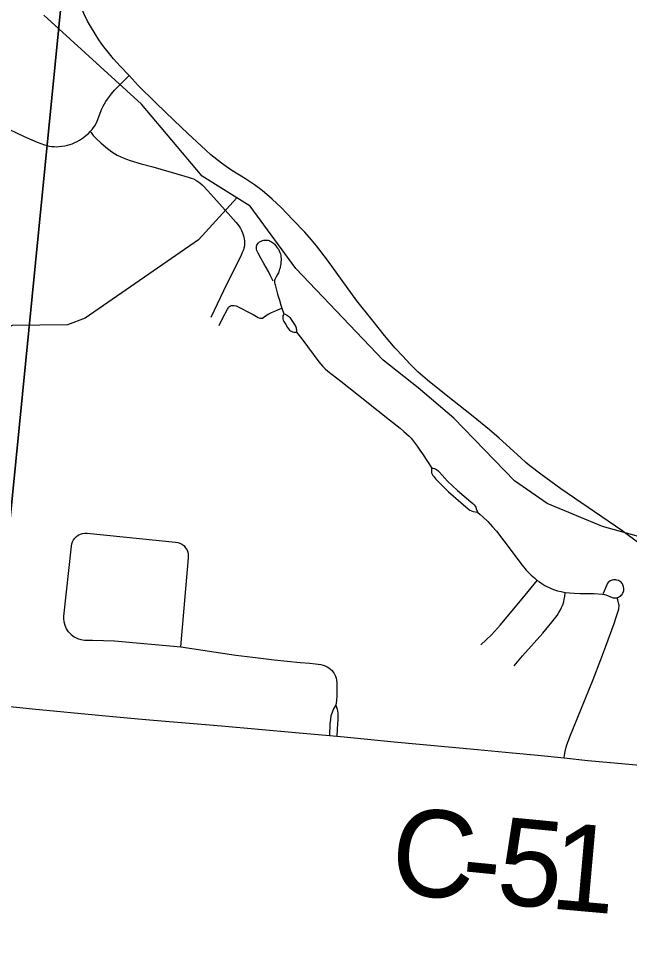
# Model space of a CAD drawing. Extents: x 0 to 34, y 0 to 22.
# Drawn here: x 25.829 to 26.229, y 14.002 to 14.618 of the extents above; entities that cross this region are included whole.
import ezdxf

# ---------------------------------------------------------------- set-up
doc = ezdxf.new("R2010")
doc.units = 0
for name, color, linetype in [('GM_X_City_Street', 7, 'Continuous'), ('GM_X_County_Road', 7, 'Continuous'), ('GM_X_County_Road_Text', 7, 'Continuous'), ('GM_X_Minor_River', 7, 'Continuous'), ('GM_X_Section', 7, 'Continuous')]:
    doc.layers.add(name, color=color, linetype=linetype)

msp = doc.modelspace()

# ---------------------------------------------------------------- linework, layer by layer
at = {"layer": 'GM_X_City_Street'}
msp.add_line((26.00175, 14.4284), (26.00308, 14.42476), dxfattribs=at)
for points in [[(25.87622, 14.54403), (25.87748, 14.54535), (25.87842, 14.54667), (25.87925, 14.54786), (25.88003, 14.54926), (25.88077, 14.55082), (25.88392, 14.55901), (25.88463, 14.5606), (25.88554, 14.56226), (25.88648, 14.5638), (25.8875, 14.56533), (25.88874, 14.56705), (25.89008, 14.56873), (25.89211, 14.57108), (25.8947, 14.5738), (25.89799, 14.57704), (25.90163, 14.58064)], [(25.81826, 14.54775), (25.83287, 14.54078), (25.84146, 14.53708), (25.84621, 14.53534), (25.84781, 14.53487), (25.84932, 14.53456), (25.85097, 14.53429), (25.85254, 14.53418), (25.8541, 14.53413), (25.85575, 14.53421), (25.85763, 14.53442), (25.85956, 14.53472), (25.86125, 14.53508), (25.86289, 14.53557), (25.86449, 14.5361), (25.86622, 14.53684), (25.86762, 14.53754), (25.86911, 14.53836), (25.87045, 14.53919), (25.87177, 14.54017), (25.87341, 14.54145), (25.87501, 14.54276), (25.87622, 14.54403)], [(25.87622, 14.54403), (25.87676, 14.54336), (25.87821, 14.54155), (25.8805, 14.53917), (25.88326, 14.53658), (25.88646, 14.53382), (25.89035, 14.53088), (25.8921, 14.52968), (25.89396, 14.52862), (25.8958, 14.52762), (25.89776, 14.52675), (25.89995, 14.52589), (25.90233, 14.52507), (25.90953, 14.52297), (25.91722, 14.52088), (25.93811, 14.51495), (25.94029, 14.51428), (25.94234, 14.51363), (25.94395, 14.51301), (25.94539, 14.51227), (25.94662, 14.5114), (25.94795, 14.51042), (25.94946, 14.50919), (25.95081, 14.50787), (25.95709, 14.50093), (25.96823, 14.48845), (25.9716, 14.48471), (25.97284, 14.48313), (25.97387, 14.48164), (25.97453, 14.48058), (25.97518, 14.47941), (25.97588, 14.47787), (25.9764, 14.4764), (25.97675, 14.4752), (25.97703, 14.47387), (25.9772, 14.47252), (25.97729, 14.47124), (25.97728, 14.47026), (25.97715, 14.46924), (25.97687, 14.46784), (25.97652, 14.4667), (25.9758, 14.46484), (25.97505, 14.46314), (25.96343, 14.4398), (25.95511, 14.42245)], [(25.99597, 14.4462), (25.99433, 14.44958), (25.99285, 14.45242), (25.98987, 14.45776), (25.98797, 14.46122), (25.98616, 14.46442), (25.98576, 14.46529), (25.98539, 14.46619), (25.98519, 14.46705), (25.98506, 14.46804), (25.98512, 14.46902), (25.98539, 14.46977), (25.98572, 14.47038), (25.98613, 14.47092), (25.98711, 14.47178), (25.98778, 14.47218), (25.98859, 14.4726), (25.98929, 14.47285), (25.98999, 14.47301), (25.99087, 14.47308), (25.9918, 14.47305), (25.99266, 14.47288), (25.99336, 14.47268), (25.99406, 14.47239), (25.99484, 14.47198), (25.99554, 14.47149), (25.99623, 14.47092), (25.99684, 14.47032), (25.99784, 14.46919), (25.9987, 14.46804), (25.9994, 14.46705), (25.99994, 14.46604), (26.00043, 14.46496), (26.00077, 14.46406), (26.00101, 14.4631), (26.00112, 14.46217), (26.00121, 14.46107), (26.0012, 14.46), (26.00109, 14.45856), (26.00097, 14.45745), (26.0008, 14.45634), (26.00063, 14.45541), (26.00032, 14.45427), (26.00004, 14.45334), (25.99969, 14.45235), (25.9994, 14.4516), (25.9989, 14.45061), (25.99796, 14.44892), (25.99748, 14.44806), (25.99718, 14.44727), (25.99697, 14.44651), (25.99689, 14.44588), (25.99692, 14.44518), (25.99706, 14.44436), (25.99723, 14.44372), (25.99893, 14.43767), (26.00006, 14.43363), (26.00104, 14.43043), (26.00175, 14.4284)], [(25.96072, 14.41721), (25.96292, 14.42162), (25.96611, 14.42788), (25.96644, 14.42854), (25.96685, 14.42912), (25.96738, 14.42961), (25.96804, 14.42998), (25.9687, 14.43018), (25.96989, 14.43031), (25.97055, 14.43027), (25.97174, 14.43002), (25.98284, 14.42436), (25.9861, 14.42248), (25.98727, 14.422), (25.9879, 14.42192), (25.98905, 14.42204), (25.99102, 14.42345), (25.99308, 14.4248), (25.99484, 14.4257), (25.99701, 14.42662), (25.99916, 14.42743), (26.00175, 14.4284)], [(26.00308, 14.42476), (26.00275, 14.4241), (26.00245, 14.42336), (26.00225, 14.4225), (26.00234, 14.42155), (26.00262, 14.42069), (26.003, 14.41986), (26.00423, 14.41781), (26.00546, 14.41588), (26.00677, 14.41415), (26.00726, 14.41371), (26.00782, 14.41338), (26.00871, 14.41305), (26.00959, 14.41284), (26.01035, 14.41272), (26.01119, 14.41268)], [(26.00308, 14.42476), (26.00394, 14.42447), (26.00468, 14.42414), (26.00533, 14.42377), (26.00599, 14.42328), (26.00682, 14.42229), (26.00817, 14.4204), (26.00994, 14.41773), (26.01064, 14.41662), (26.01107, 14.41564), (26.01117, 14.4149), (26.01123, 14.4142), (26.01119, 14.41268)], [(26.01119, 14.41268), (26.01469, 14.40835), (26.01848, 14.40338), (26.02595, 14.39332), (26.02714, 14.39183), (26.02856, 14.39022), (26.03004, 14.38881), (26.03182, 14.38725), (26.04022, 14.38064), (26.05187, 14.37158), (26.06475, 14.36132), (26.07225, 14.35541), (26.07924, 14.34987), (26.08152, 14.34787), (26.08334, 14.34632), (26.08498, 14.34475), (26.08634, 14.34332), (26.08774, 14.34167), (26.08909, 14.33995), (26.09041, 14.3381), (26.09212, 14.33566), (26.09386, 14.33318), (26.09713, 14.32816), (26.09993, 14.32388)], [(26.09993, 14.32388), (26.09977, 14.32314), (26.09964, 14.3224), (26.09964, 14.32162), (26.09974, 14.32079), (26.10005, 14.31989), (26.10063, 14.31903), (26.10126, 14.31822), (26.10256, 14.31668), (26.10552, 14.31348), (26.11084, 14.3084), (26.11887, 14.30141), (26.12365, 14.29712), (26.12472, 14.29634), (26.12582, 14.29581), (26.12698, 14.29548), (26.12975, 14.29506)], [(26.09993, 14.32388), (26.10079, 14.32376), (26.10171, 14.32354), (26.10258, 14.32322), (26.10322, 14.32277), (26.10393, 14.32215), (26.10471, 14.32129), (26.10667, 14.31915), (26.11025, 14.31521), (26.11345, 14.31216), (26.11682, 14.30906), (26.12537, 14.30177), (26.12665, 14.3007), (26.12759, 14.29971), (26.12819, 14.29895), (26.12862, 14.29815), (26.12901, 14.29719), (26.12975, 14.29506)], [(26.12975, 14.29506), (26.13158, 14.29355), (26.13354, 14.29182), (26.13658, 14.28877), (26.13967, 14.28538), (26.14217, 14.28248), (26.14711, 14.27617), (26.15903, 14.26037), (26.16172, 14.25703), (26.16336, 14.25529), (26.16505, 14.25373), (26.16706, 14.25192), (26.16899, 14.25036)], [(25.862, 14.2167), (25.86069, 14.21868), (25.85973, 14.22084), (25.85914, 14.22314), (25.85894, 14.2255), (25.85902, 14.227), (25.86388, 14.27276), (25.86414, 14.27419), (25.86462, 14.27556), (25.8653, 14.27684), (25.86617, 14.278), (25.8672, 14.27901), (25.86843, 14.27989), (25.86979, 14.28056)], [(25.86979, 14.28056), (25.87123, 14.28101), (25.87273, 14.28122), (25.87424, 14.28119), (25.93214, 14.27541), (25.93358, 14.27515), (25.93497, 14.27467), (25.93626, 14.27399), (25.93743, 14.27311), (25.93846, 14.27207)], [(25.9355, 14.20686), (25.94063, 14.2652), (25.94067, 14.26599), (25.94053, 14.26763), (25.9401, 14.26922), (25.9394, 14.27072), (25.93846, 14.27207)], [(26.13209, 14.20824), (26.13906, 14.21477), (26.14498, 14.22125), (26.15022, 14.2276), (26.15906, 14.23834), (26.16899, 14.25036)], [(26.16899, 14.25036), (26.17035, 14.24937), (26.17191, 14.24833), (26.17387, 14.24708), (26.1752, 14.24629), (26.17666, 14.24559), (26.17838, 14.24487), (26.18023, 14.24426), (26.18227, 14.24358), (26.18467, 14.24297), (26.18724, 14.24247)], [(26.22123, 14.23895), (26.2222, 14.23936), (26.2228, 14.23971), (26.2234, 14.24011), (26.22395, 14.2406), (26.22447, 14.24113), (26.22486, 14.24175), (26.22517, 14.24238), (26.2254, 14.24303), (26.22556, 14.24372), (26.22566, 14.2445), (26.22563, 14.24526), (26.22546, 14.24614), (26.22524, 14.24678), (26.22497, 14.24744), (26.22468, 14.24803), (26.22431, 14.2486), (26.22384, 14.24915), (26.22332, 14.24957), (26.22279, 14.2499), (26.22221, 14.25019), (26.22114, 14.25052), (26.22043, 14.25068), (26.21962, 14.25078), (26.2189, 14.25073), (26.21805, 14.25058), (26.21724, 14.25035), (26.21658, 14.24997), (26.21553, 14.24912), (26.21511, 14.24864), (26.21473, 14.24801), (26.21441, 14.24743), (26.21211, 14.24166)], [(26.1538, 14.19433), (26.15932, 14.20105), (26.17254, 14.21589), (26.17859, 14.22296), (26.1819, 14.22745), (26.18309, 14.22928), (26.18418, 14.23115), (26.1849, 14.23256), (26.18553, 14.23395), (26.18593, 14.23503), (26.1863, 14.2363), (26.18667, 14.23811), (26.18691, 14.2398), (26.18724, 14.24247)], [(26.18724, 14.24247), (26.19016, 14.24223), (26.19317, 14.24199), (26.19696, 14.24182), (26.20625, 14.24167), (26.21166, 14.24138), (26.21207, 14.24133), (26.2123, 14.24131), (26.21296, 14.24119), (26.21387, 14.2409), (26.21793, 14.23921), (26.2187, 14.23899), (26.21932, 14.23888), (26.21998, 14.23886), (26.22123, 14.23895)], [(26.18651, 14.13417), (26.18676, 14.13593), (26.18726, 14.13828), (26.18817, 14.14205), (26.19029, 14.14803), (26.20549, 14.18545), (26.21048, 14.19867), (26.21378, 14.20722), (26.21927, 14.22221), (26.22067, 14.22619), (26.22157, 14.22895), (26.22229, 14.23157), (26.22244, 14.23248), (26.22248, 14.23326), (26.22248, 14.23404), (26.22235, 14.23486), (26.2222, 14.23565), (26.22195, 14.23651), (26.22166, 14.23762), (26.22123, 14.23895)], [(25.862, 14.2167), (25.86367, 14.21493), (25.86561, 14.21346), (25.86778, 14.21235), (25.8701, 14.21163), (25.87252, 14.21131), (25.87765, 14.21115), (25.89222, 14.21073), (25.9355, 14.20686)], [(25.9355, 14.20686), (25.97163, 14.20143), (25.98262, 14.20002), (25.99676, 14.19846), (26.01379, 14.1967), (26.02, 14.19613), (26.02379, 14.19579), (26.02558, 14.19554), (26.02718, 14.19526), (26.02866, 14.19488), (26.03006, 14.19439), (26.03133, 14.19386), (26.03252, 14.19312), (26.03363, 14.19226), (26.03454, 14.19127), (26.03528, 14.19037), (26.03593, 14.18942), (26.03647, 14.18851), (26.03684, 14.18757), (26.03716, 14.18646), (26.03751, 14.18496), (26.0377, 14.1835), (26.03779, 14.18199), (26.03778, 14.17869), (26.03766, 14.17478), (26.03745, 14.17179), (26.03713, 14.1687)], [(26.03713, 14.1687), (26.03626, 14.16743), (26.03556, 14.1662), (26.03503, 14.16513), (26.03454, 14.16385), (26.03413, 14.16278), (26.03384, 14.16167), (26.03347, 14.15941), (26.03306, 14.15641), (26.03291, 14.14876)], [(26.03713, 14.1687), (26.03754, 14.16734), (26.03787, 14.16607), (26.03815, 14.16475), (26.03832, 14.16348), (26.0384, 14.16241), (26.0384, 14.16126), (26.03832, 14.15933), (26.0382, 14.15645), (26.03799, 14.15292), (26.03772, 14.14835)]]:
    msp.add_lwpolyline(points, dxfattribs=at)
at = {"layer": 'GM_X_County_Road'}
for points in [[(25.87453, 14.61636), (25.8721, 14.62136), (25.87108, 14.62355), (25.87017, 14.62561), (25.8697, 14.62676), (25.8688, 14.62904), (25.8682, 14.63064), (25.86634, 14.63651), (25.86541, 14.63972), (25.86393, 14.64482), (25.86299, 14.64839), (25.86216, 14.65181), (25.8617, 14.65383), (25.86061, 14.6601), (25.85984, 14.66673), (25.85945, 14.67503), (25.85955, 14.6783)], [(25.90163, 14.58064), (25.8958, 14.58678), (25.89155, 14.59158), (25.88704, 14.59713), (25.88509, 14.59954), (25.88336, 14.60185), (25.88196, 14.60398), (25.87939, 14.60809), (25.87649, 14.61292), (25.87453, 14.61636)], [(25.95195, 14.53194), (25.94009, 14.54271), (25.93129, 14.55129), (25.91914, 14.56292), (25.90768, 14.57426), (25.90163, 14.58064)], [(25.97786, 14.51306), (25.96902, 14.51855), (25.96674, 14.52006), (25.96212, 14.52336), (25.9553, 14.5289), (25.95195, 14.53194)], [(26.22427, 14.28304), (26.18449, 14.3102), (26.17119, 14.3198), (26.164, 14.32533), (26.16153, 14.32738), (26.15811, 14.33046), (26.14403, 14.34343), (26.13777, 14.3489), (26.12701, 14.35755), (26.11347, 14.36838), (26.09951, 14.37937), (26.09712, 14.38134), (26.09106, 14.38666), (26.0855, 14.39208), (26.08084, 14.397), (26.07591, 14.40238), (26.06892, 14.41066), (26.06059, 14.42111), (26.0509, 14.43331), (26.03149, 14.45981), (26.02432, 14.46928), (26.02104, 14.47323), (26.01664, 14.47815), (26.00895, 14.48637), (26.00116, 14.49436), (25.99543, 14.49975), (25.99367, 14.50133), (25.98874, 14.50548), (25.98379, 14.50914), (25.97786, 14.51306)], [(26.23889, 14.27216), (26.23457, 14.27527), (26.22427, 14.28304)], [(25.70784, 14.17932), (25.71166, 14.17894), (25.71413, 14.1787), (25.74385, 14.17578), (25.76149, 14.17407), (25.77959, 14.17237), (25.83833, 14.16621), (25.88413, 14.16191), (25.90271, 14.16022), (25.9151, 14.1592), (25.93589, 14.15745), (25.96221, 14.15514)], [(25.96221, 14.15514), (26.01067, 14.15074), (26.03291, 14.14876)], [(26.03291, 14.14876), (26.03772, 14.14835), (26.04248, 14.14794)], [(26.04248, 14.14794), (26.07522, 14.1447), (26.12974, 14.13958), (26.15273, 14.13753), (26.16927, 14.13598), (26.18651, 14.13417)], [(26.18651, 14.13417), (26.20201, 14.1325), (26.21687, 14.13111), (26.26021, 14.12719), (26.30228, 14.12314), (26.31835, 14.12133), (26.33074, 14.12006), (26.36939, 14.11675), (26.39565, 14.11435)]]:
    msp.add_lwpolyline(points, dxfattribs=at)
at = {"layer": 'GM_X_Minor_River'}
for points in [[(26.24705, 14.27571), (26.21159, 14.28554), (26.17547, 14.3007), (26.15415, 14.31555), (26.11438, 14.3566), (26.09088, 14.37643), (26.0681, 14.39435), (26.01088, 14.45434), (25.98097, 14.49518), (25.9495, 14.5148), (25.90985, 14.56191), (25.84577, 14.62015)], [(25.97221, 14.50064), (25.94715, 14.4731), (25.87291, 14.42184), (25.86144, 14.41752), (25.82502, 14.41712), (25.79897, 14.40436), (25.77309, 14.38135), (25.75202, 14.37115), (25.71621, 14.36353), (25.68216, 14.36801), (25.66081, 14.36275), (25.63319, 14.32839), (25.62283, 14.32253), (25.61427, 14.31169), (25.60942, 14.27763), (25.59796, 14.27369), (25.57728, 14.28321), (25.55662, 14.27452), (25.50382, 14.27066), (25.49275, 14.26709), (25.45836, 14.25488), (25.39712, 14.24663)]]:
    msp.add_lwpolyline(points, dxfattribs=at)
at = {"layer": 'GM_X_Section'}
for points in [[(25.86182, 14.67437), (25.76091, 13.65822), (24.71962, 13.7501), (24.8195, 14.77309)], [(26.85675, 14.57345), (26.75942, 13.56709), (25.76091, 13.65822), (25.86182, 14.67437)]]:
    msp.add_lwpolyline(points, close=True, dxfattribs=at)

# ---------------------------------------------------------------- texts
at = {"layer": 'GM_X_County_Road_Text'}
for s, rotation, p in [('C', 354.39019, (26.07133, 14.04603)), ('5', 354.4944, (26.14111, 14.03918)), ('1', 354.90014, (26.17639, 14.03578)), ('-', 354.40259, (26.11779, 14.04147))]:
    msp.add_text(s, height=0.05682, rotation=rotation, dxfattribs=at).set_placement(p)

doc.saveas('drawing.dxf')
